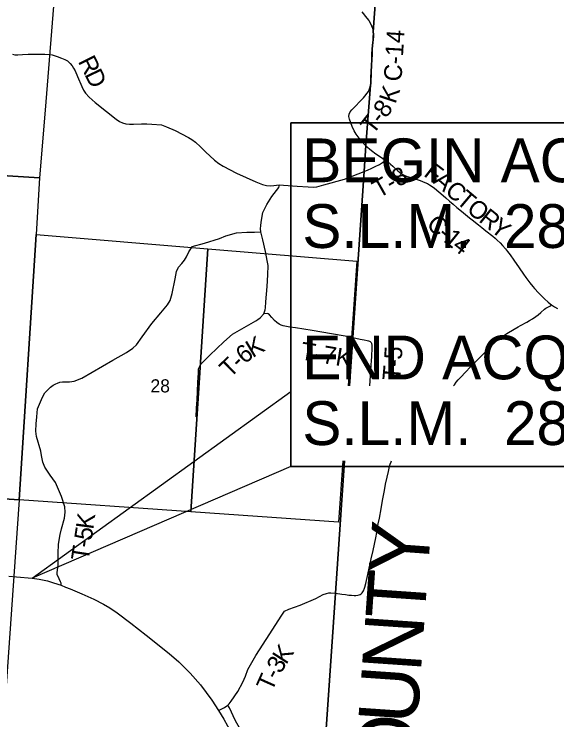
# Model space of a CAD drawing. Extents: x 0 to 34, y 0 to 22.
# Drawn here: x 5.404 to 7.141, y 16.952 to 19.209 of the extents above; entities that cross this region are included whole.
import ezdxf

# ---------------------------------------------------------------- set-up
doc = ezdxf.new("R2010")
doc.units = 0
for name, color, linetype in [('GM_X_Corporation', 7, 'Continuous'), ('GM_X_County_Road', 7, 'Continuous'), ('GM_X_County_Road_Text', 7, 'Continuous'), ('GM_X_County_Text', 7, 'Continuous'), ('GM_X_Section_Text', 7, 'Continuous'), ('GM_X_Township_Road', 7, 'Continuous'), ('GM_X_Township_Road_Text', 7, 'Continuous'), ('GM_X_Township_Text', 7, 'Continuous'), ('GM_X_US_Route', 7, 'Continuous'), ('SH_Text', 7, 'Continuous')]:
    doc.layers.add(name, color=color, linetype=linetype)

msp = doc.modelspace()

# ---------------------------------------------------------------- linework, layer by layer
at = {"layer": 'GM_X_Corporation'}
for points in [[(6.4774, 18.0202), (6.488, 18.1751), (6.5242, 18.7061), (6.5297, 18.7882), (6.5448, 18.981), (6.5455, 18.9878), (6.5461, 19.0017), (6.5463, 19.0089), (6.5469, 19.0218), (6.548, 19.0466), (6.5487, 19.0617), (6.5495, 19.082), (6.5503, 19.0966), (6.5514, 19.1091), (6.5523, 19.1179), (6.5529, 19.1264), (6.5537, 19.1382), (6.5541, 19.1447), (6.5536, 19.1514), (6.5814, 19.5334), (6.6608, 20.6694), (6.6768, 20.9), (2.1, 20.9), (2.1, 14.1)], [(6.4559, 17.7802), (6.4419, 17.5848), (5.9698, 17.6172), (6.0241, 18.4583), (6.5013, 18.419), (6.4729, 18.0202)], [(6.368, 16.4127), (6.4323, 17.3579), (6.4611, 17.7802)]]:
    msp.add_lwpolyline(points, dxfattribs=at)
for points in [[(4.5379, 19.7849), (5.5693, 19.7272), (5.5363, 19.3151), (5.5032, 18.9017), (5.4857, 18.6848), (4.465, 18.749)], [(5.4857, 18.6848), (5.4744, 18.5035), (5.4208, 17.6557), (4.3947, 17.724), (4.465, 18.749)], [(5.4744, 18.5035), (6.0241, 18.4583), (5.9698, 17.6172), (5.4208, 17.6557)], [(5.4208, 17.6557), (5.3461, 16.6042), (4.3249, 16.693), (4.3947, 17.724)]]:
    msp.add_lwpolyline(points, close=True, dxfattribs=at)
at = {"layer": 'GM_X_County_Road'}
for points in [[(6.5166, 19.2154), (6.5329, 19.1959), (6.5392, 19.1883), (6.5449, 19.1788), (6.5481, 19.171), (6.5513, 19.1631), (6.5538, 19.1509)], [(6.5538, 19.1509), (6.5543, 19.1441), (6.5539, 19.1376), (6.5532, 19.1258), (6.5525, 19.1174), (6.5516, 19.1086), (6.5505, 19.096), (6.5497, 19.0815), (6.5489, 19.0612), (6.5482, 19.0461), (6.5471, 19.0212), (6.5465, 19.0084), (6.5463, 19.0011), (6.5457, 18.9872), (6.545, 18.9805)], [(5.399, 19.08), (5.4063, 19.0782), (5.4165, 19.0782), (5.4312, 19.079), (5.4489, 19.08), (5.4796, 19.0803), (5.5028, 19.0803), (5.5174, 19.0799), (5.5263, 19.0779), (5.542, 19.0727), (5.5564, 19.0676), (5.5666, 19.0631), (5.5749, 19.0587), (5.5842, 19.0505), (5.59, 19.0431), (5.5945, 19.0357), (5.5992, 19.0274), (5.6073, 19.0093), (5.6205, 18.977), (5.6262, 18.9659), (5.633, 18.9559), (5.6441, 18.943), (5.6639, 18.9258), (5.7003, 18.8977), (5.7307, 18.8724), (5.7413, 18.8657), (5.7516, 18.8609), (5.7619, 18.8581), (5.7735, 18.8567), (5.786, 18.8571), (5.8123, 18.8579), (5.8287, 18.858), (5.8449, 18.8568), (5.8757, 18.8542), (5.8915, 18.8486), (5.9192, 18.8361), (5.9619, 18.8146), (5.9733, 18.8078), (5.9846, 18.7992), (6.0003, 18.7845), (6.0168, 18.7688), (6.0456, 18.7413), (6.0593, 18.7305), (6.073, 18.7225), (6.116, 18.7004), (6.1773, 18.6724), (6.1992, 18.6639), (6.2117, 18.6605), (6.2263, 18.6594), (6.2538, 18.6623), (6.2667, 18.662), (6.3096, 18.6587), (6.3454, 18.6564), (6.3618, 18.6556), (6.373, 18.6566), (6.395, 18.6623), (6.4618, 18.6804), (6.5244, 18.7055)], [(6.5299, 18.7876), (6.5481, 18.7726), (6.5613, 18.7624), (6.5798, 18.7497), (6.5924, 18.7409), (6.6043, 18.7327), (6.6091, 18.7289), (6.6166, 18.7224), (6.632, 18.708), (6.6377, 18.7031), (6.6421, 18.6996), (6.648, 18.6959), (6.6547, 18.6926), (6.6622, 18.6896), (6.6741, 18.6858), (6.6906, 18.6807), (6.7041, 18.6762), (6.7186, 18.6707), (6.7271, 18.667), (6.734, 18.6629), (6.7422, 18.6575), (6.7492, 18.6523), (6.7639, 18.6401), (6.7775, 18.6284), (6.7859, 18.621), (6.7975, 18.6107), (6.8094, 18.6007), (6.8213, 18.5907), (6.8355, 18.5787), (6.8488, 18.5675), (6.8618, 18.5568), (6.8701, 18.5504), (6.8904, 18.535), (6.9011, 18.5265), (6.9143, 18.5161), (6.936, 18.4986), (6.9436, 18.4922), (6.9504, 18.486), (6.9593, 18.4774), (6.9673, 18.4688), (6.9763, 18.4586), (6.9833, 18.4499), (6.9919, 18.4386), (7.0032, 18.4223), (7.0203, 18.3972), (7.0347, 18.3769), (7.0422, 18.3662), (7.0545, 18.3498), (7.0637, 18.338), (7.069, 18.3319), (7.0824, 18.318), (7.102, 18.298), (7.1128, 18.2876), (7.1194, 18.282), (7.1242, 18.2787), (7.1271, 18.2766), (7.133, 18.2731), (7.1434, 18.2674)]]:
    msp.add_lwpolyline(points, dxfattribs=at)
at = {"layer": 'GM_X_Township_Road'}
for points in [[(6.5299, 18.7876), (6.5149, 18.8038), (6.4992, 18.8246), (6.492, 18.8356), (6.4864, 18.8491), (6.4777, 18.8722), (6.4757, 18.8812), (6.476, 18.8892), (6.4799, 18.8966), (6.4848, 18.9025), (6.5223, 18.9404), (6.5379, 18.9611), (6.5413, 18.9696), (6.545, 18.9805)], [(6.5244, 18.7055), (6.5373, 18.7111), (6.5465, 18.7152), (6.5596, 18.7215), (6.5731, 18.7283), (6.5833, 18.734), (6.5878, 18.7373), (6.591, 18.7398), (6.5924, 18.7409)], [(5.5379, 18.0263), (5.5429, 18.0288), (5.5511, 18.032), (5.5593, 18.0329), (5.5819, 18.0335), (5.5964, 18.0356), (5.6206, 18.045), (5.7199, 18.1019), (5.7637, 18.1273), (5.7837, 18.1404), (5.7964, 18.1512), (5.8144, 18.177), (5.8448, 18.2193), (5.8737, 18.2532), (5.8951, 18.2796), (5.9039, 18.2928), (5.9102, 18.315), (5.9196, 18.3627), (5.9238, 18.3854), (5.9304, 18.3999), (5.9409, 18.4113), (5.9496, 18.4224), (5.9562, 18.433), (5.9639, 18.4489), (5.9693, 18.4586), (5.9746, 18.4658), (6.0131, 18.476), (6.0613, 18.4914), (6.0818, 18.4998), (6.116, 18.509), (6.149, 18.512), (6.1737, 18.5112), (6.1938, 18.5122), (6.1931, 18.5219), (6.1936, 18.5323), (6.1951, 18.5429), (6.1971, 18.556), (6.2001, 18.574), (6.2129, 18.5999), (6.2287, 18.626), (6.2513, 18.6544), (6.2538, 18.6623)], [(6.4882, 18.1746), (6.3584, 18.1973), (6.3044, 18.2059), (6.2863, 18.2082), (6.2651, 18.2123), (6.2588, 18.2147), (6.2522, 18.2179), (6.2447, 18.2228), (6.2374, 18.2294), (6.2293, 18.2392), (6.2215, 18.2471), (6.2177, 18.25), (6.2141, 18.2517), (6.2031, 18.2503), (6.2075, 18.2634), (6.2089, 18.2699), (6.21, 18.2893), (6.2138, 18.3376), (6.2157, 18.3746), (6.2171, 18.4045), (6.2146, 18.4206), (6.2084, 18.45), (6.2001, 18.4866), (6.1938, 18.5122)], [(6.8106, 18.0202), (6.813, 18.0233), (6.8193, 18.0317), (6.8256, 18.0393), (6.8333, 18.0481), (6.8483, 18.0637), (6.865, 18.0805), (6.8736, 18.0891), (6.8925, 18.1086), (6.9073, 18.1241), (6.9174, 18.1343), (6.9235, 18.1406), (6.9259, 18.1432), (6.9309, 18.1478), (6.9413, 18.1574), (6.9512, 18.1659), (6.96, 18.1728), (6.9712, 18.1807), (6.981, 18.1871), (7.0044, 18.2013), (7.0168, 18.2084), (7.0249, 18.2129), (7.0449, 18.2239), (7.054, 18.2292), (7.0629, 18.2347), (7.0737, 18.2417), (7.0814, 18.2474), (7.0895, 18.2543), (7.1019, 18.2648), (7.1062, 18.2682), (7.1099, 18.2707), (7.1139, 18.2731), (7.1182, 18.2754), (7.1215, 18.2772), (7.1242, 18.2787)], [(5.9869, 17.921), (5.9877, 17.9491), (5.9901, 17.9755), (5.9922, 18.0304), (5.9939, 18.062), (5.9943, 18.075), (5.9974, 18.0812), (6.0016, 18.0891), (6.0304, 18.1182), (6.075, 18.1612), (6.1033, 18.1855), (6.1554, 18.2156), (6.1775, 18.2278), (6.1846, 18.2327), (6.1915, 18.2375), (6.2031, 18.2503)], [(6.4882, 18.1746), (6.5112, 18.1698), (6.5242, 18.1671), (6.534, 18.1651), (6.5382, 18.1641), (6.5416, 18.1629), (6.5437, 18.1619), (6.5455, 18.1602), (6.5467, 18.1584), (6.5476, 18.1567), (6.5482, 18.1547), (6.5486, 18.1529), (6.5488, 18.1507), (6.549, 18.1451), (6.5485, 18.1321), (6.5482, 18.124), (6.5475, 18.1136), (6.5464, 18.1001), (6.5456, 18.0871), (6.5446, 18.0685), (6.5426, 18.0357), (6.5419, 18.0202)], [(5.5546, 17.3832), (5.5546, 17.3893), (5.5532, 17.394), (5.5488, 17.4037), (5.5462, 17.4088), (5.5426, 17.4163), (5.5419, 17.4235), (5.5431, 17.4311), (5.5455, 17.4485), (5.5456, 17.4735), (5.545, 17.4839), (5.5467, 17.5136), (5.5521, 17.5453), (5.5557, 17.5626), (5.5659, 17.5975), (5.5679, 17.6159), (5.5662, 17.6335), (5.5558, 17.6665), (5.5368, 17.7108), (5.5192, 17.7351), (5.503, 17.76), (5.4961, 17.7758), (5.492, 17.7975), (5.4894, 17.8117), (5.4755, 17.8585), (5.4742, 17.8755), (5.4754, 17.8984), (5.4773, 17.9207), (5.4796, 17.9468), (5.4947, 17.9842), (5.5027, 17.9976), (5.5208, 18.0164), (5.5296, 18.0221), (5.5379, 18.0263)], [(6.4325, 17.3573), (6.4525, 17.3545), (6.465, 17.3527), (6.4755, 17.3515), (6.4835, 17.3508), (6.4922, 17.3503), (6.4978, 17.3505), (6.5037, 17.3512), (6.5086, 17.3522), (6.512, 17.3537), (6.5151, 17.3557), (6.5178, 17.3583), (6.52, 17.3613), (6.5222, 17.365), (6.5234, 17.3677), (6.5244, 17.37), (6.5266, 17.3771), (6.5295, 17.3885), (6.5339, 17.4078), (6.5371, 17.4224), (6.5403, 17.4376), (6.5469, 17.4673), (6.5528, 17.494), (6.5614, 17.5347), (6.5645, 17.5512), (6.5673, 17.5658), (6.5697, 17.5786), (6.5731, 17.5969), (6.5787, 17.6269), (6.583, 17.6532), (6.5892, 17.6861), (6.5928, 17.7057), (6.5979, 17.7285), (6.602, 17.7466), (6.606, 17.762), (6.6081, 17.7699), (6.6105, 17.7774), (6.6117, 17.7802)], [(6.0583, 16.9829), (6.0777, 16.9924), (6.0884, 16.9999), (6.092, 17.0035), (6.0988, 17.0118), (6.1203, 17.0428), (6.1357, 17.0732), (6.1452, 17.092), (6.1519, 17.1136), (6.1775, 17.1579), (6.2225, 17.2274), (6.259, 17.2839), (6.27, 17.2996), (6.2833, 17.3062), (6.3202, 17.3193), (6.3695, 17.3409), (6.3937, 17.3537), (6.4039, 17.3568), (6.4119, 17.3582), (6.4181, 17.3587), (6.4325, 17.3573)], [(6.1999, 16.5816), (6.2034, 16.5833), (6.2053, 16.5862), (6.2023, 16.6003), (6.2004, 16.622), (6.2031, 16.6328), (6.2199, 16.723), (6.2205, 16.7398), (6.2196, 16.7543), (6.2156, 16.7684), (6.2079, 16.786), (6.1952, 16.8085), (6.1668, 16.853), (6.1509, 16.8811), (6.136, 16.9073), (6.1116, 16.9515), (6.094, 16.9913), (6.0884, 16.9999)]]:
    msp.add_lwpolyline(points, dxfattribs=at)
at = {"layer": 'GM_X_Township_Text'}
for points in [[(6.6768, 20.9), (6.6608, 20.6694), (6.5814, 19.5334), (6.5536, 19.1514), (6.5541, 19.1447), (6.5537, 19.1382), (6.5529, 19.1264), (6.5523, 19.1179), (6.5514, 19.1091), (6.5503, 19.0966), (6.5495, 19.082), (6.5487, 19.0617), (6.548, 19.0466), (6.5469, 19.0218), (6.5463, 19.0089), (6.5461, 19.0017), (6.5455, 18.9878), (6.5448, 18.981), (6.5297, 18.7882), (6.5242, 18.7061), (6.488, 18.1751), (6.4774, 18.0202)], [(6.4611, 17.7802), (6.4323, 17.3579), (6.368, 16.4127), (6.3333, 15.9036), (6.2987, 15.5286)]]:
    msp.add_lwpolyline(points, dxfattribs=at)
at = {"layer": 'GM_X_US_Route'}
msp.add_lwpolyline([(5.3878, 17.4121), (5.4117, 17.4102), (5.4619, 17.4055), (5.4769, 17.4038), (5.485, 17.4022), (5.5116, 17.3968), (5.53, 17.3909), (5.5546, 17.3832), (5.5687, 17.3767), (5.5836, 17.3709), (5.6214, 17.355), (5.6591, 17.3387), (5.69, 17.3227), (5.7106, 17.3104), (5.7346, 17.2942), (5.7782, 17.2618), (5.8272, 17.2229), (5.9007, 17.165), (5.9314, 17.1377), (5.9672, 17.1022), (6.0007, 17.0645), (6.0371, 17.0156), (6.0583, 16.9829), (6.0752, 16.9548), (6.0984, 16.9117)], dxfattribs=at)
at = {"layer": 'SH_Text'}
for points in [[(8.3656, 18.861), (6.2897, 18.861), (6.2897, 17.7622), (8.3656, 17.7622)], [(6.2897, 18.861), (8.3656, 18.861), (8.3656, 17.7622), (6.2897, 17.7622)], [(5.4619, 17.4055), (6.2897, 18.0022), (6.2897, 17.7622)]]:
    msp.add_lwpolyline(points, close=True, dxfattribs=at)

# ---------------------------------------------------------------- texts
at = {"layer": 'GM_X_County_Road_Text'}
for s, height, rotation, p in [('C-14', 0.05682, 86.5725, (6.6438, 18.9922)), ('R', 0.0568, 296.7256, (5.6079, 19.0576)), ('D', 0.0568, 295.4865, (5.6287, 19.0162)), ('F', 0.0568, 322.7034, (6.712, 18.6933)), ('A', 0.0568, 319.6907, (6.7419, 18.6705)), ('C', 0.0568, 319.2124, (6.7799, 18.6383)), ('T', 0.0568, 319.8082, (6.8157, 18.6074)), ('O', 0.0568, 320.8584, (6.8491, 18.5792)), ('R', 0.0568, 321.3344, (6.8883, 18.5473)), ('C', 0.0568, 318.5361, (6.7204, 18.5311)), ('Y', 0.0568, 321.0168, (6.9246, 18.5182)), ('-', 0.0568, 320.0607, (6.7566, 18.4991)), ('1', 0.0568, 321.1217, (6.7754, 18.4834)), ('4', 0.0568, 321.9516, (6.8033, 18.4609))]:
    msp.add_text(s, height=height, rotation=rotation, dxfattribs=at).set_placement(p)
at = {"layer": 'GM_X_County_Text'}
for s, rotation, p in [('Y', 85.8022, (6.7272, 17.4106)), ('T', 86.0344, (6.7174, 17.2695)), ('N', 86.066, (6.7059, 17.1024)), ('U', 86.0747, (6.6944, 16.9353)), ('O', 86.0758, (6.683, 16.7682))]:
    msp.add_text(s, height=0.1894, rotation=rotation, dxfattribs=at).set_placement(p)
at = {"layer": 'GM_X_Section_Text'}
msp.add_text('28', height=0.04186, rotation=0, dxfattribs=at).set_placement((5.8407, 17.9993))
at = {"layer": 'GM_X_Township_Road_Text'}
for s, height, rotation, p in [('K', 0.0568, 71.6726, (6.6245, 18.9193)), ('8', 0.0568, 53.0228, (6.5941, 18.8735)), ('T', 0.0568, 51.8408, (6.5527, 18.8207)), ('-', 0.0568, 52.0447, (6.5791, 18.8543)), ('T-8', 0.05682, 29.5674, (6.5714, 18.619)), ('K', 0.0568, 30.8438, (6.1673, 18.1084)), ('6', 0.0568, 37.7463, (6.1411, 18.088)), ('T-7K', 0.05682, 350.587, (6.3178, 18.1052)), ('5', 0.0568, 86.3891, (6.6448, 18.1026)), ('T', 0.0568, 44.4606, (6.0953, 18.0432)), ('-', 0.0568, 43.8572, (6.1255, 18.0728)), ('-', 0.0568, 85.3148, (6.6428, 18.0782)), ('T', 0.0568, 85.16, (6.6392, 18.0357)), ('K', 0.0568, 82.4619, (5.6578, 17.5594)), ('5', 0.0568, 81.3195, (5.6523, 17.5236)), ('T', 0.0568, 81.0668, (5.6421, 17.4583)), ('-', 0.0568, 81.1185, (5.6487, 17.5003)), ('K', 0.0568, 57.199, (6.2747, 17.1268)), ('3', 0.0568, 58.0795, (6.2565, 17.0975)), ('T', 0.0568, 65.8308, (6.2292, 17.0402)), ('-', 0.0568, 62.0952, (6.2462, 17.078))]:
    msp.add_text(s, height=height, rotation=rotation, dxfattribs=at).set_placement(p)
at = {"layer": 'SH_Text'}
for s, p in [('BEGIN ACQUISITION', (6.3267, 18.671)), ('S.L.M.  28.73', (6.3267, 18.461)), ('END ACQUISITION', (6.3267, 18.041)), ('S.L.M.  28.76', (6.3267, 17.831))]:
    msp.add_text(s, height=0.14, dxfattribs=at).set_placement(p)

doc.saveas('drawing.dxf')
